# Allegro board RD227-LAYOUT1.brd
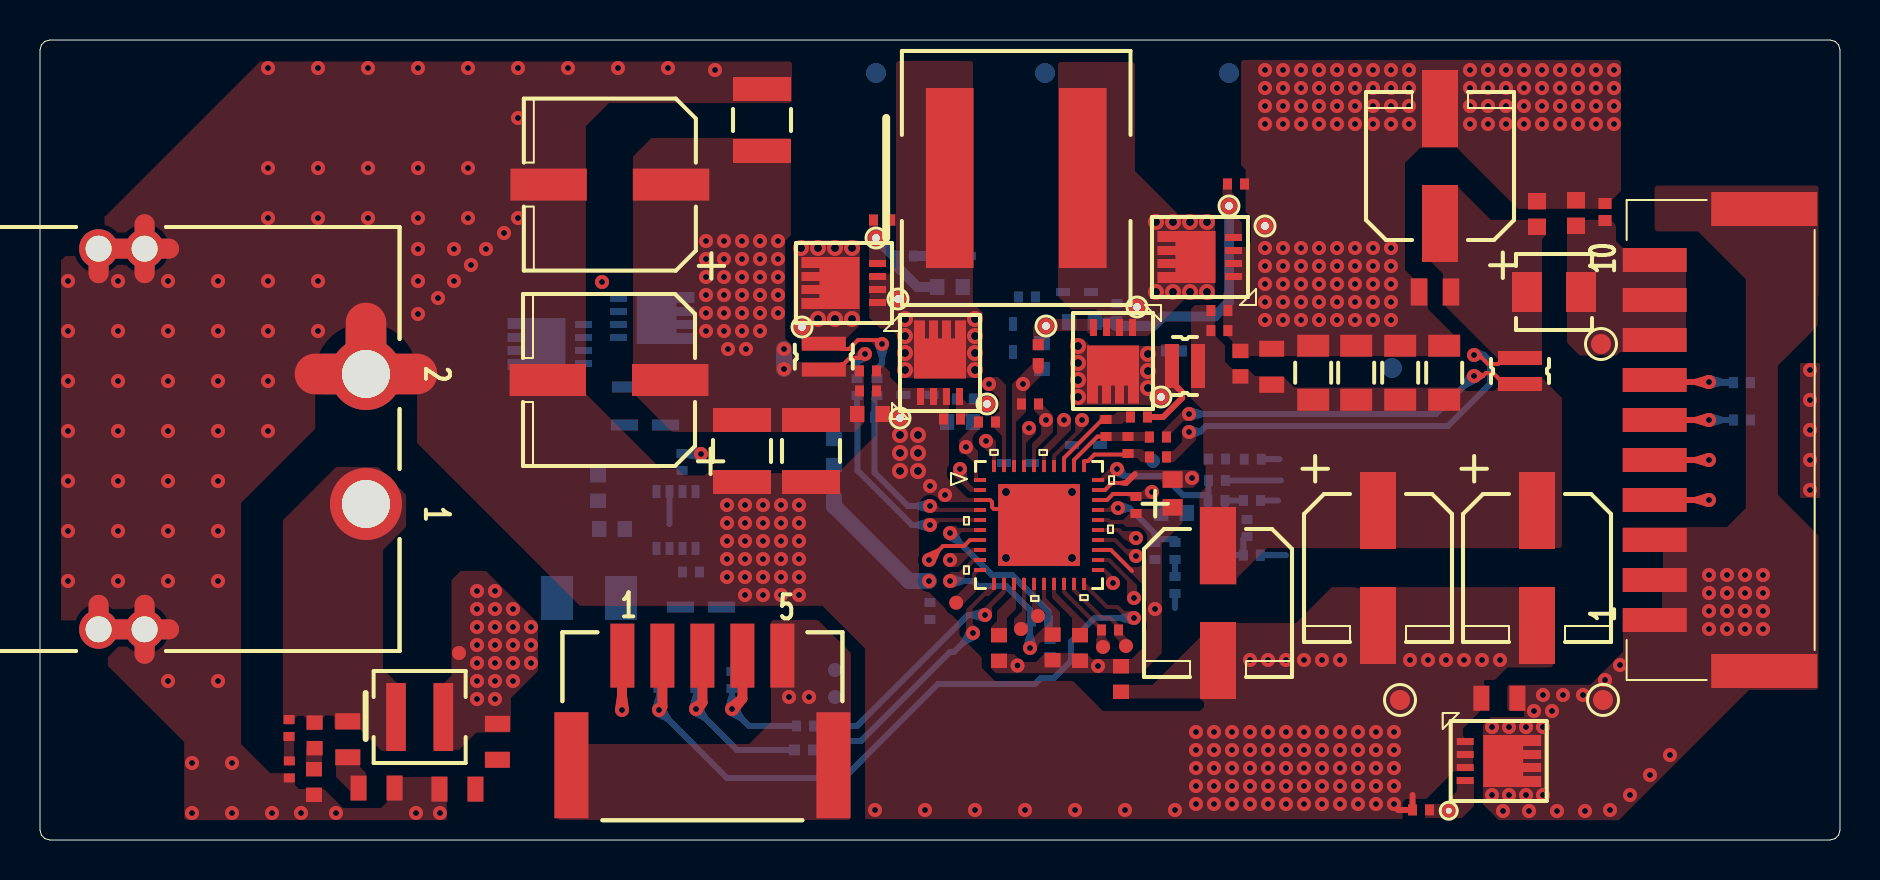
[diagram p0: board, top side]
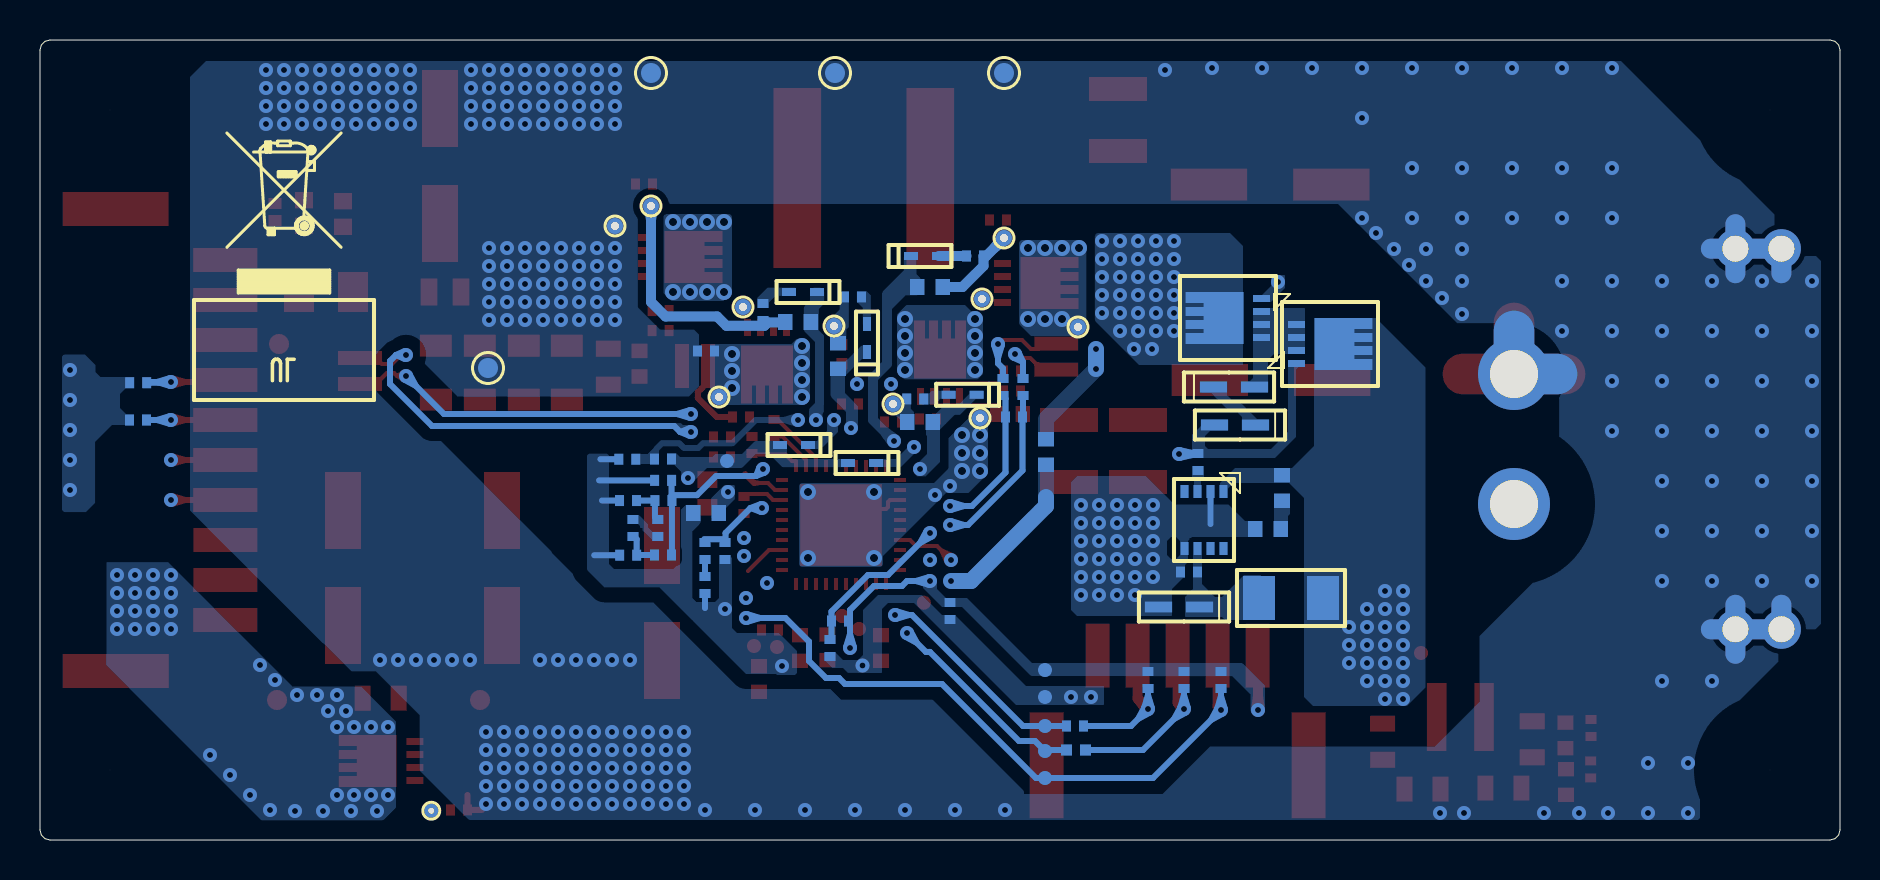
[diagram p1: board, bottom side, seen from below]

Outline 90 x 40 mm; copper layers: TOP, CONDUCTIVE2, CONDUCTIVE3, BOTTOM. Coordinates in mm from the lower left corner of the outline.
Outline path: 0,39.5 0.07,39.75 0.25,39.93 0.5,40 89.5,40 89.75,39.93 89.93,39.75 90,39.5 90,0.5 89.93,0.25 89.75,0.07 89.5,0 0.5,0 0.25,0.07 0.07,0.25 0,0.5 0,39.5

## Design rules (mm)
constraint set DEFAULT: 

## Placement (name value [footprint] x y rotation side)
C101  -  [KC00060AKP]  15.39 5.03 90 top
C102  -  [KC00060AKP]  16.83 2.6 180 top
C103  -  [KCK03340AKP]  36.1 36 270 top
C104  -  [KC00080AKP]  41.5 21.3 180 top
C105  -  [KC01340AKP]  13.73 5.23 90 top
C106  -  [KC01340AKP]  13.7 2.9 90 top
C107  -  [DC837K]  28.49 32.77 0 top
C108  -  [KCK03340AKP]  35.1 19.45 90 top
C109  -  [DC834K]  41.4 22.45 180 top
C110  -  [DC834K]  12.45 5.6 90 top
C111  -  [DC834K]  12.47 3.53 90 top
C112  -  [DC837K]  28.45 23 0 top
C113  -  [KCK03340AKP]  38.55 19.45 90 top
C114  -  [DC834K]  41.4 23.45 180 top
C115  -  [KC00060AKP]  22.87 4.91 90 top
C116  -  [KC00060AKP]  20.87 2.55 0 top
C117  -  [DC834K]  47.35 20.9 0 top
C118  -  [DC834K#2]  32.55 13.4 0 bottom
C119  -  [KC01540AKP01#2]  56.7 24.45 180 bottom
C120  -  [DC834K]  49.5 21.8 180 top
C121  -  [KC00080AKP#2]  27.9 17.6 270 bottom
C122  -  [KC00080AKP#2]  28.6 15.55 0 bottom
C123  -  [DC843R]  58.9 11.85 90 top
C124  -  [KC00140AKP]  70.21 23.36 270 top
C125  -  [KC00060AKP]  61.58 23.66 270 top
C126  -  [DC843R]  74.85 13.6 90 top
C127  -  [KC00140AKP]  68.01 23.36 270 top
C128  -  [KC00080AKP]  60.02 23.82 270 top
C129  -  [DC843R]  66.9 13.6 90 top
C130  -  [KC00140AKP]  65.81 23.36 270 top
C131  -  [DC834K]  58.97 25.47 180 top
C132  -  [KC00140AKP]  63.66 23.36 270 top
C133  -  [KC01540AKP01]  58.97 26.47 180 top
C134  -  [KCK02380AKP01]  74.85 31.3 270 top
C135  -  [DC843R]  70 33.7 270 top
C136  -  [KCK02380AKP01]  76.8 31.35 270 top
C137  -  [KC01540AKP01]  78.25 31.4 270 top
C138  -  [KC00060AKP]  72.97 7.09 0 top
C139  -  [KC00080AKP#2]  56.7 16.35 0 bottom
C140  -  [DC834K]  54.8 16.75 90 top
C141  -  [DC834K#2]  44.5 11.45 270 bottom
C142  -  [KC01670AKP]  50.63 9.63 270 top
C143  -  [KC01560AKP]  56.63 17.33 270 top
C144  -  [DC834K#2]  41.3 21.15 180 bottom
C145  -  [KC00080AKP]  47.95 9.6 270 top
C146  -  [KC00080AKP]  52 9.6 270 top
C147  -  [DC834K]  53.3 20.6 90 top
C148  -  [DC834K]  54.4 19.75 90 top
C149  -  [DC834K#2]  85.1 21 0 bottom
C150  -  [DC834K#2]  85.09 22.86 0 bottom
C151  -  [DC834K#2]  55.75 14.45 270 bottom
C152  -  [DC834K#2]  56.75 12.75 270 bottom
C153  -  [DC834K#2]  58.85 17.98 0 bottom
C154  -  [DC834K#2]  60.6 16.97 0 bottom
C155  -  [DC834K#2]  60.35 15.6 270 bottom
CN101  -  [LOCAL_HVH_280_2P_6_5_1]  16.3 16.8 270 top
CN102  -  [LOCAL_502352_0501]  33.12 5.69 0 top
CN103  -  [LOCAL_502352_1000]  84 20 90 top
D101  -  [D8K022]  33.05 11.65 180 bottom
D102  -  [D8101D1AKP]  48.9 18.85 180 bottom
D103  -  [D8101D1AKP]  45.75 29.2 0 bottom
D104  -  [D8101D1AKP]  43.87 22.26 180 bottom
D105  -  [D8101D1AKP]  48.65 25.1 270 bottom
D106  -  [D8101D1AKP]  51.85 27.4 180 bottom
D107  -  [D8101D1AKP]  52.3 19.75 180 bottom
D108  -  [D8K022]  30.25 20.75 180 bottom
D109  -  [D8K022]  30.3 22.65 0 bottom
FL101  -  [KC00080AKP#2]  39.7 19.4 90 bottom
IC101  -  [SN00281AKP]  31.8 16 0 bottom
IC102  -  [LOCAL_MAX25432BATLGV_1]  49.95 15.75 0 top
L101  -  [LOCAL_XEL_4030_471ME_1]  18.98 6.15 0 top
L102  -  [LOCAL_XAL1010_472MED]  48.81 33.1 0 top
L103  -  [LOCAL_IHLP1212BZEVR2_1]  75.7 27.4 0 top
NOREF  -  [unnamed]  86.5 36.5 0 top
NOREF#2  -  [unnamed]  3.5 3.5 0 top
NOREF#3  -  [unnamed]  3.5 36.5 0 top
NOREF#4  -  [unnamed]  86.5 3.5 0 top
NOREF#5  -  [#2]  77.8 31.35 180 bottom
NOREF#6  -  [#2]  73.3 22 180 bottom
Q101  -  [SN00612AKP]  25.5 24.8 270 bottom
Q102  -  [SN00612AKP]  30.6 26.1 90 bottom
Q103  -  [SN00612AKP]  40.2 27.85 90 top
Q104  -  [SN00612AKP]  45 23.85 0 top
Q105  -  [SN00612AKP]  53.65 23.95 180 top
Q106  -  [SN00612AKP]  58 29.15 90 top
Q107  -  [SN00612AKP]  72.94 3.95 270 top
R101  -  [KC00080AKP#2]  46 20.9 0 bottom
R102  -  [KC00080AKP#2]  45.5 27.65 180 bottom
R103  -  [DC934K#3]  43.25 29.2 180 bottom
R104  -  [LOCAL_KRL2012]  39.19 24.17 90 top
R105  -  [LOCAL_KRL2012]  57.25 23.7 0 top
R106  -  [LOCAL_KRL2012]  74 23.45 90 top
R107  -  [DC934K#3]  46.24 22.05 0 bottom
R108  -  [DC934K]  42.1 31 180 top
R109  -  [DC934K]  45.6 21.05 0 top
R110  -  [DR820RF]  27.45 12.1 0 bottom
R111  -  [DC934K#2]  49.91 24.29 90 top
R112  -  [DC934K]  59.8 32.8 180 top
R113  -  [DC934K#3]  49.35 27.15 0 bottom
R114  -  [DC934K#3]  53.85 26.4 270 bottom
R115  -  [KC00080AKP#2]  50.1 24.2 90 bottom
R116  -  [KC00080AKP#2]  52.1 25.9 0 bottom
R117  -  [DR824K#2]  32.1 18.9 270 bottom
R119  -  [DR810K]  69.75 27.4 0 top
R120  -  [DR824K]  69.05 1.5 0 top
R121  -  [DR824K#2]  34.6 8 90 bottom
R122  -  [DR824K#2]  32.8 8 90 bottom
R123  -  [DC934K#3]  41.85 22.65 270 bottom
R124  -  [DC934K#3]  40.85 22.65 270 bottom
R125  -  [DR824K#2]  30.95 8 90 bottom
R126  -  [DR824K]  53.5 10.5 180 top
R127  -  [DC934K#4]  38.2 4.5 0 bottom
R128  -  [DC934K#3]  38.25 5.7 0 bottom
R129  -  [KC00080AKP]  54.05 8.05 90 top
R130  -  [DC934K]  54.95 21.15 180 top
R131  -  [DC934K]  55.9 20.15 180 top
R132  -  [DC934K]  55.9 19.15 180 top
R133  -  [DR824K#2]  56.75 14.45 270 bottom
R134  -  [DC934K#3]  50 10.95 180 bottom
R135  -  [DR824K#2]  50.5 9.6 90 bottom
R136  -  [KC00050AKP]  58.83 16.97 0 bottom
R137  -  [DC934K#3]  60.64 19.04 180 bottom
R138  -  [DR824K#2]  59.11 15.6 270 bottom
R139  -  [DR824K#2]  58.85 19.05 180 bottom
R140  -  [DR824K#2]  58.85 14.25 0 bottom
R141  -  [DR824K#2]  60.59 14.24 0 bottom
TP101  -  [TL0_7_A_NOMM]  20.95 9.35 0 top
TP102  -  [TL0_7_A_NOMM]  39.7 17.15 180 bottom
TP103  -  [LOCAL_TL0_4_TH_A]  38.1 25.65 180 bottom
TP104  -  [LOCAL_TL0_4_TH_A]  41.8 30.1 180 bottom
TP105  -  [LOCAL_TL0_4_TH_A]  42.9 27.05 180 bottom
TP106  -  [LOCAL_TL0_4_TH_A]  47.35 21.8 0 top
TP107  -  [LOCAL_TL0_4_TH_A]  43 21.1 0 top
TP108  -  [LOCAL_TL0_4_TH_A]  56.05 22.15 0 top
TP109  -  [LOCAL_TL0_4_TH_A]  50.3 25.7 180 bottom
TP110  -  [LOCAL_TL0_4_TH_A]  54.85 26.65 180 bottom
TP111  -  [LOCAL_TL0_4_TH_A]  59.45 31.7 180 bottom
TP112  -  [LOCAL_TL0_4_TH_A]  61.25 30.7 180 bottom
TP113  -  [LOCAL_TP_100_A]  78.05 24.8 0 top
TP114  -  [LOCAL_TL0_4_TH_A]  70.44 1.46 0 top
TP115  -  [LOCAL_TP_100_A]  78.15 7 0 top
TP116  -  [LOCAL_TP_100_A]  68 7 0 top
TP117  -  [TL0_7_A_NOMM]  39.75 8.5 180 bottom
TP118  -  [TL0_7_A_NOMM]  39.75 7.15 180 bottom
TP119  -  [TL0_7_A_NOMM]  55.65 18.95 180 bottom
TP120  -  [TL0_7_A_NOMM]  54.3 9.7 0 top
TP121  -  [TL0_7_A_NOMM]  53.15 9.65 0 top
TP122  -  [TL0_7_A_NOMM]  39.75 3.1 180 bottom
TP123  -  [TL0_7_A_NOMM]  39.75 4.45 180 bottom
TP124  -  [TL0_7_A_NOMM]  39.75 5.7 180 bottom
TP125  -  [TL0_7_A_NOMM]  45.81 11.86 0 top
TP126  -  [TL0_7_A_NOMM]  49.05 10.55 0 top
TP127  -  [TL0_7_A_NOMM]  49.9 11.2 0 top
TP131  -  [LOCAL_TP_100_A]  67.6 23.6 180 bottom
TP132  -  [LOCAL_TP_100_A]  59.45 38.35 180 bottom
TP133  -  [LOCAL_TP_100_A]  50.25 38.35 180 bottom
TP134  -  [LOCAL_TP_100_A]  41.8 38.35 180 bottom

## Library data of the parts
C101 C102 C115 C116 = GDM03S00003P: alternate symbols: (T:KC00060AKP;B:KC00060BKP)
C103 C108 C113 = GAS030000261: alternate symbols: (T:KCK03340AKP;B:KCK03340BKP)
C104 C121 C122 C128 C139 C145 C146 = GDM03S000024: alternate symbols: (T:KC00080AKP;B:KC00080BKP)
C105 C106 = GAS030000041: alternate symbols: (T:KC01340AKP;B:KC01340BKP)
C107 C112 = GDM030001780: alternate symbols: (T:DC837K;B:DC937K)
C109 C114 C117 C118 C120 C131 C140 C141 C155 = G924015104Q0: alternate symbols: (T:DC834K;B:DC934K)
C110 C111 = G5103106P106: alternate symbols: (T:DC834K;B:DC934K)
C119 C133 C137 = GAS030000078: alternate symbols: (T:KC01540AKP01,DC834K,KC01540AKP;B:KC01540BKP01,DC834K,KC01540BKP)
C123 C126 C129 C135 = GDM030000304: alternate symbols: (T:DC843R;B:DC943R)
C124 C127 C130 C132 = GDM03S000017: alternate symbols: (T:KC00140AKP;B:KC00140BKP)
C125 C138 = GDM03S000036: alternate symbols: (T:KC00060AKP;B:KC00060BKP)
C134 C136 = GAS030000086: alternate symbols: (T:KCK02380AKP01;B:KCK02380BKP01)
C142 = GDM030002537: alternate symbols: (T:KC01670AKP;B:KC01670BKP)
C143 = GDM030002140: alternate symbols: (T:KC01560AKP;B:KC01560BKP)
C144 C147 C148 C151 = G5103105X103: alternate symbols: (T:DC834K;B:DC934K)
C149 C150 = G5103106G107: alternate symbols: (T:DC834K;B:DC934K)
C152 = G36030133517: alternate symbols: (T:DC834K;B:DC934K)
C153 = G510310FQ104: alternate symbols: (T:DC834K;B:DC934K)
C154 = G510310E1104: alternate symbols: (T:DC834K;B:DC934K)
CN101 = HVH-280-2P-6_5DS: alternate symbols: (T:Local_HVH_280_2P_6_5_1;B:Local_HVH_280_2P_6_5_1_B)
CN102 = 502352-0501: alternate symbols: (T:Local_502352_0501;B:Local_502352_0501_B)
CN103 = 502352-1000: alternate symbols: (T:Local_502352_1000;B:Local_502352_1000_B)
D101 D108 D109 = K4200015: alternate symbols: (T:D8K022;B:D9K022)
D102-D107 = GDM42S000008: alternate symbols: (T:D8101D1AKP;B:D8101D1BKP)
FL101 = GDM130000101: alternate symbols: (T:KC00080AKP;B:KC00080BKP)
IC101 = GDM410000462: alternate symbols: (T:SN00281AKP;B:SN00281BKP)
IC102 = MAX25432BATLGV+
L101 = XEL-4030-471MEC: alternate symbols: (T:Local_XEL_4030_471ME_1;B:Local_XEL_4030_471ME_1_B)
L102 = XAL1010-472MED: alternate symbols: (T:Local_XAL1010_472MED;B:Local_XAL1010_472MED_B)
L103 = IHLP1212BZEVR22M5A: alternate symbols: (T:Local_IHLP1212BZEVR2_1;B:Local_IHLP1212BZEVR2_1_B)
Q101-Q107 = K4100929: alternate symbols: (T:SN00612AKP;B:SN00612BKP)
R101 R102 R115 R116 R129 = G8800256207A: alternate symbols: (T:KC00080AKP;B:KC00080BKP)
R103 R107-R109 R111-R114 R123 R124 R127 R128 R130-R132 R134 R137 = GAS010000128: alternate symbols: (T:DC934K,DR824K,KC01310AKP,DR924K;B:DC934K,DR824K,KC01310BKP,DR924K)
R104 R105 = KRL2012E-M-R003-F
R106 = KRL2012E-M-R005-F: alternate symbols: (T:Local_KRL2012;B:Local_KRL2012_B)
R110 = G510110RM109: alternate symbols: (T:DR820RF;B:DR901RF)
R117 = G510110CB102: alternate symbols: (T:DR824K;B:DR924K)
R119 = G510110AC101: alternate symbols: (T:DR810K;B:DR910K)
R120 R125 = G510110EF108: alternate symbols: (T:DR824K;B:DR924K)
R121 R122 = G510110E7102: alternate symbols: (T:DR824K;B:DR924K)
R126 R133 R135 R138-R141 = G510110M9109: alternate symbols: (T:DR824K;B:DR924K)
R136 = GDM010002829: alternate symbols: (T:KC00050AKP;B:KC00050BKP)
TP101 TP102 TP117-TP127 = TL0.7_noMM: alternate symbols: (T:TL0_7_A_noMM;B:TL0_7_B_noMM)
TP103-TP112 TP114 = TL0.4_TH: alternate symbols: (T:Local_TL0_4_TH_A,Local_TL0_3_TH_A;B:Local_TL0_4_TH_B,Local_TL0_3_TH_B)
TP113 TP115 TP116 TP131-TP134 = TP-100: alternate symbols: (T:Local_TP_100_A;B:Local_TP_100_B)

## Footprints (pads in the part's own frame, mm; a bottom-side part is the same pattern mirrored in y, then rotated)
D8K022
  rect 1.36x0.55 smd: A(-1.025,0) C(1.025,0)
D8101D1AKP
  rect 0.7x0.4 smd: A(-0.7,0) C(0.7,0)
DC834K
  rect 0.45x0.55 smd: 1(-0.425,0) 2(0.425,0)
DC834K#2
  rect 0.45x0.55 smd: 1(0.425,0) 2(-0.425,0)
DC837K
  rect 3.82x1.6 smd: 1(-3.06,0) 2(3.06,0)
DC843R
  rect 3.85x1.8 smd: 1(-2.875,0) 2(2.875,0)
DC934K
  rect 0.45x0.55 smd: 1(-0.425,0) 2(0.425,0)
DC934K#2
  rect 0.55x0.55 smd: 1(-0.475,0) 2(0.475,0)
DC934K#3
  rect 0.45x0.55 smd: 1(0.425,0) 2(-0.425,0)
DC934K#4
  rect 0.55x0.55 smd: 1(0.475,0) 2(-0.475,0)
DR810K
  rect 0.83x1.35 smd: 1(-0.8,0) 2(0.8,0)
DR820RF
  rect 1.6x2.2 smd: 1(1.6,0) 2(-1.6,0)
DR824K
  rect 0.45x0.55 smd: 1(-0.425,0) 2(0.425,0)
DR824K#2
  rect 0.45x0.55 smd: 1(0.425,0) 2(-0.425,0)
KC00050AKP
  rect 0.45x0.55 smd: 1(0.425,0) 2(-0.425,0)
KC00060AKP
  rect 0.8x1.25 smd: 1(-0.9,0) 2(0.9,0)
KC00080AKP
  rect 0.72x0.8 smd: 1(-0.64,0) 2(0.64,0)
KC00080AKP#2
  rect 0.72x0.8 smd: 1(0.64,0) 2(-0.64,0)
KC00140AKP
  rect 1.1x1.6 smd: 1(-1.35,0) 2(1.35,0)
KC01340AKP
  rect 0.72x0.8 smd: 1(-0.64,0) 2(0.64,0)
KC01540AKP01
  rect 0.55x0.65 smd: 1(-0.425,0) 2(0.425,0)
KC01540AKP01#2
  rect 0.45x0.55 smd: 1(0.425,0) 2(-0.425,0)
KC01560AKP
  rect 0.83x1 smd: 1(-0.695,0) 2(0.695,0)
KC01670AKP
  rect 0.72x0.8 smd: 1(-0.64,0) 2(0.64,0)
KCK02380AKP01
  rect 0.82x0.9 smd: 1(-0.64,0) 2(0.64,0)
KCK03340AKP
  rect 1.2x2.9 smd: 1(-1.55,0) 2(1.55,0)
LOCAL_502352_0501
  rect 1.2x3.2 smd: 1(-4,3.53) 2(-2,3.53) 3(0,3.53) 4(2,3.53) 5(4,3.53)
  rect 1.7x5.3 smd: 1T(-6.55,-1.95) 2T(6.55,-1.95)
LOCAL_502352_1000
  rect 1.2x3.2 smd: 1(-9,3.265) 2(-7,3.265) 3(-5,3.265) 4(-3,3.265) 5(-1,3.265) 6(1,3.265) 7(3,3.265) 8(5,3.265) 9(7,3.265) 10(9,3.265)
  rect 1.7x5.3 smd: 1T(-11.55,-2.215) 2T(11.55,-2.215)
LOCAL_HVH_280_2P_6_5_1
  round 3.6 hole 2.4: 1(0,0) 2(-6.5,0)
  round 1.95 hole 1.3: 1T(6.265,-13.37) 2T(6.265,-11.07) 3T(-12.765,-11.07) 4T(-12.765,-13.37)
LOCAL_IHLP1212BZEVR2_1
  custom 0.375x0.375 smd: 1(-1.35,0) 2(1.35,0)
LOCAL_KRL2012
  custom 0.175x0.175 smd: 1(-0.65,0) 2(0.65,0)
LOCAL_MAX25432BATLGV_1
  custom 0.05x0.05 smd: 1(-2.948,2.25) 2(-2.948,1.75) 3(-2.948,1.25) 4(-2.948,0.75) 5(-2.948,0.25) 6(-2.948,-0.25) 7(-2.948,-0.75) 8(-2.948,-1.25) 9(-2.948,-1.75) 10(-2.948,-2.25) 11(-2.25,-2.948) 12(-1.75,-2.948) 13(-1.25,-2.948) 14(-0.75,-2.948) 15(-0.25,-2.948) 16(0.25,-2.948) 17(0.75,-2.948) 18(1.25,-2.948) 19(1.75,-2.948) 20(2.25,-2.948) 21(2.948,-2.25) 22(2.948,-1.75) 23(2.948,-1.25) 24(2.948,-0.75) 25(2.948,-0.25) 26(2.948,0.25) 27(2.948,0.75) 28(2.948,1.25) 29(2.948,1.75) 30(2.948,2.25) 31(2.25,2.948) 32(1.75,2.948) 33(1.25,2.948) 34(0.75,2.948) 35(0.25,2.948) 36(-0.25,2.948) 37(-0.75,2.948) 38(-1.25,2.948) 39(-1.75,2.948) 40(-2.25,2.948)
  custom 1.022x1.022 smd: 41(0,0)
LOCAL_TL0_4_TH_A
  round 0.7 hole 0.3: 1(0,0)
LOCAL_TP_100_A
  custom 0.25x0.25 smd: 1(0,0)
LOCAL_XAL1010_472MED
  custom 0.595x0.595 smd: 1(-3.325,0) 2(3.325,0)
LOCAL_XEL_4030_471ME_1
  custom 0.245x0.245 smd: 1(-1.185,0) 2(1.185,0)
SN00281AKP
  rect 0.4x0.65 smd: 1(-0.975,-1.425) 2(-0.325,-1.425) 3(0.325,-1.425) 4(0.975,-1.425) 5(0.975,1.425) 6(0.325,1.425) 7(-0.325,1.425) 8(-0.975,1.425)
SN00612AKP
  rect 0.35x0.85 smd: 1(-0.975,-1.675) 2(-0.325,-1.675) 3(0.325,-1.675) 4(0.975,-1.675)
  custom 0.65x0.65 smd: 5(0,0.675)
TL0_7_A_NOMM
  round 0.7 smd: 1(0,0)
unnamed
  round 0.01 hole 3 unplated: (0,0)

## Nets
GND_A: C139.1 C140.1 C141.1 C142.2 C143.2 C145.2 C146.2 C149.1 C150.1 C151.1 C152.1 C153.1 C154.1 CN102.1T CN102.2T CN102.5 IC102.23 IC102.26 R129.2 R135.2 R137.2 R141.1 TP118.1
GND_P: C102.1 C103.1 C104.1 C106.1 C107.1 C108.1 C109.1 C111.1 C112.1 C113.1 C114.1 C116.1 C118.1 C119.2 C122.1 C123.1 C124.1 C125.1 C126.1 C127.1 C128.1 C129.1 C130.1 C131.1 C132.1 C133.1 C134.1 C135.1 C136.1 C137.1 C138.1 CN101.1T CN101.2 CN101.2T CN101.3T CN101.4T D101.A IC101.2 IC101.5 IC102.3 IC102.41 Q104.1 Q104.2 Q104.3 Q106.1 Q106.2 Q106.3 Q107.1 Q107.2 Q107.3 R109.1 R112.1 R119.1 R120.1 R129.1 TP107.1 TP112.1 TP116.1 TP131.1 TP132.1 TP133.1 TP134.1
VBAT: C139.2 C140.2 FL101.2 IC102.28 TP102.1
VBUS: C136.2 C137.2 CN103.8 CN103.9 CN103.10 L103.2 TP113.1
VDD: C141.2 C142.1 CN102.1 IC102.9 IC102.16 R121.1 R122.1 R125.1 R134.1 TP117.1
VIN: C101.2 C105.2 C110.2 CN101.1 L101.1
VIN2: C115.2 C121.2 IC101.1 L101.2 Q101.5 R110.2 TP101.1
ADDR: IC102.34 R137.1 R139.2
ALERT: CN102.2 IC102.20 R125.2 TP122.1
BIAS: C143.1 D102.A D107.A IC102.29 R139.1 TP119.1
BST1: C117.1 D102.C IC102.1
BST2: C120.1 D107.C IC102.36
CSN1: Q103.5 R104.2 R123.2 TP103.1
CSN2: C134.2 C135.2 L103.1 R106.2 R119.2 R132.1
CSP1: C103.2 C104.2 C107.2 C108.2 C109.2 C112.2 C113.2 C114.2 FL101.1 Q102.5 R104.1 R124.2
CSP2: C119.1 Q105.5 R105.1 R130.1 TP108.1
DH1: D103.C IC102.40 R102.2
DH1_Q: Q103.4 R102.1 R103.1 R108.2 TP104.1
DH2: D105.C IC102.37 R115.2
DH2_Q: Q105.4 R111.2 R113.1 R115.1 TP109.1
DL1: D104.C IC102.2 R101.2
DL1_Q: Q104.4 R101.1 R107.1 R109.2 TP106.1
DL2: D106.C IC102.35 R116.2
DL2_Q: Q106.4 R112.2 R114.1 R116.1 TP111.1
GDRV: IC102.8 Q107.4 R120.2 TP114.1
HVCC1: C150.2 CN103.7 IC102.25
HVCC2: C149.2 CN103.6 IC102.24
HVDM: CN103.5 IC102.21
HVDP: CN103.4 IC102.22
HVEN: IC102.6 R134.2 R135.1
LX1: C117.2 IC102.39 L102.1 Q103.1 Q103.2 Q103.3 Q104.5 R108.1 TP105.1
LX2: C120.2 IC102.38 L102.2 Q105.1 Q105.2 Q105.3 Q106.5 R111.1 TP110.1
OUT: C123.2 C124.2 C125.2 C126.2 C127.2 C128.2 C129.2 C130.2 C131.2 C132.2 C133.2 R105.2 R106.1 R131.1
SCL: CN102.3 R122.2 R127.2
SDA: CN102.4 R121.2 R128.2
SHLD_SNS: C138.2 CN103.1 CN103.1T CN103.2 CN103.2T CN103.3 IC102.7 Q107.5 TP115.1
SIG310: C151.2 IC102.27 R133.2
SIG311: C152.2 R133.1
SIG313: C154.2 R136.1 R138.2
SIG316: C155.1 R140.1 R141.2
SIG317: C155.2 R138.1
SIG318: C153.2 IC102.30 R136.2 R140.2
SIG319: C147.1 C148.2 IC102.32 R131.2
SIG324: C148.1 IC102.31 R132.2
SIG328: C147.2 IC102.33 R130.2
SIG335: C144.1 IC102.5 R124.1
SIG337: C144.2 IC102.4 R123.1
SIG341: IC102.10 TP125.1
SIG344: IC102.19 R126.1 TP120.1
SIG345: IC102.18 R126.2 TP121.1
SIG346: C145.1 IC102.13
SIG347: C146.1 IC102.17
SIG349: IC102.14 TP126.1
SIG350: IC102.15 TP127.1
SIG369: IC102.11 R127.1 TP123.1
SIG370: IC102.12 R128.1 TP124.1
SIG422: C118.2 D101.C IC101.6 R110.1
SIG424: D103.A R103.2
SIG425: D104.A R107.2
SIG426: D109.A Q101.1 Q101.2 Q101.3 Q102.1 Q102.2 Q102.3
SIG427: C101.1 C102.2
SIG428: C105.1 C106.2
SIG429: C110.1 C111.2
SIG432: C121.1 C122.2
SIG434: D105.A R113.2
SIG435: D106.A R114.2
SIG439: C115.1 C116.2
SIG446: IC101.3 R117.1
SIG449: D108.C D109.C
SIG450: D108.A Q101.4 Q102.4 R117.2

Pads without a net: IC101 4 7 8

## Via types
v1: diameter 0.7, hole 0.3, TOP to BOTTOM, 446 vias
v2: diameter 0.8, hole 0.4, TOP to BOTTOM, 40 vias

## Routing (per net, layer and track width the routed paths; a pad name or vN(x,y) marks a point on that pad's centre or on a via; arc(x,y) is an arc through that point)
GND_A: length 8.7
  TOP w0.2: 54.6,13.45 53.55,14.5 IC102.23
  BOTTOM w0.3: C154.1 61.9,16.97 ; C153.1 62.05,17.98 ; 61.11,19.04 61.98,19.04 ; R141.1 62.29,14.24 ; C152.1 56.75,11.6
  vias: v1(37.45,7.15) v1(38.45,7.15) v1(48.88,8.72) v1(52.9,8.7) v1(55.75,11.55) v1(88.5,23.5) v1(88.5,22) v1(88.5,20.5) v1(88.5,19) v1(88.5,17.5)
GND_P: length 97.7
  TOP w0.2: IC102.3 47.5,17 47.6,16.9 47.6,16.65 47.7,16.55 49.15,16.55 IC102.41
  TOP w0.3: 67.9,1.5 R120.1 68.63,2.25
  TOP w1: CN101.3T 5.23,28.34 ; CN101.3T CN101.4T 2.93,28.34 ; CN101.3T 6.46,29.57 ; CN101.3T 5.23,30.79 ; 2.93,11.76 CN101.1T CN101.2T ; CN101.2T 6.46,10.54 ; CN101.2T 5.23,9.31 ; CN101.2T 5.23,11.76
  TOP w2.032: CN101.2 18.85,23.3 ; CN101.2 16.3,25.85 ; CN101.2 13.75,23.3
  CONDUCTIVE2 w1: CN101.3T 5.23,28.09 ; CN101.3T 6.71,29.57 ; CN101.3T 5.23,31.04 ; CN101.3T CN101.4T 2.93,28.06 ; CN101.2T 5.23,9.06 ; CN101.2T 5.23,12.01 ; CN101.2T CN101.1T 2.93,12.01 ; CN101.2T 6.71,10.54
  CONDUCTIVE2 w2.032: CN101.2 16.3,25.6 ; CN101.2 14,23.3 ; CN101.2 16.3,21.6 ; CN101.2 18.6,23.3
  CONDUCTIVE3 w1: CN101.2T 6.71,10.54 ; CN101.2T 5.23,12.01 ; CN101.2T CN101.1T 2.93,12.01 ; CN101.2T 5.23,9.06 ; CN101.3T 5.23,31.04 ; CN101.3T CN101.4T 2.93,27.97 ; CN101.3T 5.23,27.97 ; CN101.3T 6.71,29.57
  CONDUCTIVE3 w2.032: 16.3,25.6 CN101.2 ; CN101.2 14,23.3 ; CN101.2 18.6,23.3 ; CN101.2 16.3,21.65
  BOTTOM w0.3: IC101.2 31.48,15.8
  BOTTOM w1: 6.46,29.57 CN101.3T ; CN101.3T 5.23,28.34 ; CN101.3T CN101.4T 2.93,28.34 ; CN101.3T 5.23,30.79 ; CN101.2T CN101.1T 2.93,11.76 ; CN101.2T 6.46,10.54 ; CN101.2T 5.23,11.76 ; CN101.2T 5.23,9.31
  BOTTOM w2.032: 14.15,23.3 CN101.2 16.3,25.45
  vias: v1(1.4,27.95) v1(1.4,25.45) v1(1.4,22.95) v1(1.4,20.45) v1(1.4,17.95) v1(1.4,15.45) v1(1.4,12.95) v1(3.9,27.95) v1(3.9,25.45) v1(3.9,22.95) v1(3.9,20.45) v1(3.9,17.95) v1(3.9,15.45) v1(3.9,12.95) v1(6.4,27.95) v1(6.4,25.45) v1(6.4,22.95) v1(6.4,20.45) v1(6.4,17.95) v1(6.4,15.45) v1(6.4,12.95) v1(6.4,7.95) v1(7.6,3.85) v1(7.6,1.35) v1(8.9,27.95) v1(8.9,25.45) v1(8.9,22.95) v1(8.9,20.45) v1(8.9,17.95) v1(8.9,15.45) v1(8.9,12.95) v1(8.9,7.95) v1(9.6,3.85) v1(9.6,1.35) v1(11.4,38.6) v1(11.4,33.6) v1(11.4,31.1) v1(11.4,27.95) v1(11.4,25.45) v1(11.4,22.95) v1(11.4,20.45) v1(11.6,1.35) v1(13.05,1.35) v1(13.9,38.6) v1(13.9,33.6) v1(13.9,31.1) v1(13.9,27.95) v1(13.9,25.45) v1(14.8,1.35) v1(16.4,38.6) v1(16.4,33.6) v1(16.4,31.1) v1(18.8,1.35) v1(18.9,38.6) v1(18.9,33.6) v1(18.9,31.1) v1(18.9,29.55) v1(18.9,27.95) v1(18.9,26.3) v1(19.9,27.1) v1(20,1.35) v1(20.7,29.55) v1(20.7,27.95) v1(21.4,38.6) v1(21.4,33.6) v1(21.4,31.1) v1(21.55,28.75) v1(22.3,29.55) v1(23.2,30.35) v1(23.9,38.6) v1(23.9,36.1) v1(23.9,31.1) v1(26.4,38.6) v1(28.9,38.6) v1(31.4,38.6) v1(33.75,38.5) v1(34.35,16.75) v1(34.35,15.85) v1(34.35,14.95) v1(34.35,14.05) v1(34.35,13.15) v1(35.25,16.75) v1(35.25,15.85) v1(35.25,14.95) v1(35.25,14.05) v1(35.25,13.15) v1(35.25,12.25) v1(36.15,16.75) v1(36.15,15.85) v1(36.15,14.95) v1(36.15,14.05) v1(36.15,13.15) v1(36.15,12.25) v1(37.05,16.75) v1(37.05,15.85) v1(37.05,14.95) v1(37.05,14.05) v1(37.05,13.15) v1(37.05,12.25) v1(37.95,16.75) v1(37.95,15.85) v1(37.95,14.95) v1(37.95,14.05) v1(37.95,13.15) v1(37.95,12.25) v1(41.75,1.5) v1(44.25,1.5) v1(44.5,17.7) v1(45.25,17.25) v1(46.75,1.5) v1(49.25,1.5) v1(51.75,1.5) v1(54.25,1.5) v1(56.75,1.5) v1(57.8,5.4) v1(57.8,4.5) v1(57.8,3.6) v1(57.8,2.7) v1(57.8,1.8) v1(58.7,5.4) v1(58.7,4.5) v1(58.7,3.6) v1(58.7,2.7) v1(58.7,1.8) v1(59.6,5.4) v1(59.6,4.5) v1(59.6,3.6) v1(59.6,2.7) v1(59.6,1.8) v1(60.5,9) v1(60.5,5.4) v1(60.5,4.5) v1(60.5,3.6) v1(60.5,2.7) v1(60.5,1.8) v1(61.25,38.5) v1(61.25,37.6) v1(61.25,36.7) v1(61.25,35.8) v1(61.25,29.6) v1(61.25,28.7) v1(61.25,27.8) v1(61.25,26.9) v1(61.25,26) v1(61.4,9) v1(61.4,5.4) v1(61.4,4.5) v1(61.4,3.6) v1(61.4,2.7) v1(61.4,1.8) v1(62.15,38.5) v1(62.15,37.6) v1(62.15,36.7) v1(62.15,35.8) v1(62.15,29.6) v1(62.15,28.7) v1(62.15,27.8) v1(62.15,26.9) v1(62.15,26) v1(62.3,9) v1(62.3,5.4) v1(62.3,4.5) v1(62.3,3.6) v1(62.3,2.7) v1(62.3,1.8) v1(63.05,38.5) v1(63.05,37.6) v1(63.05,36.7) v1(63.05,35.8) v1(63.05,29.6) v1(63.05,28.7) v1(63.05,27.8) v1(63.05,26.9) v1(63.05,26) v1(63.2,9) v1(63.2,5.4) v1(63.2,4.5) v1(63.2,3.6) v1(63.2,2.7) v1(63.2,1.8) v1(63.95,38.5) v1(63.95,37.6) v1(63.95,36.7) v1(63.95,35.8) v1(63.95,29.6) v1(63.95,28.7) v1(63.95,27.8) v1(63.95,26.9) v1(63.95,26) v1(64.1,9) v1(64.1,5.4) v1(64.1,4.5) v1(64.1,3.6) v1(64.1,2.7) v1(64.1,1.8) v1(64.85,38.5) v1(64.85,37.6) v1(64.85,36.7) v1(64.85,35.8) v1(64.85,29.6) v1(64.85,28.7) v1(64.85,27.8) v1(64.85,26.9) v1(64.85,26) v1(65,9) v1(65,5.4) v1(65,4.5) v1(65,3.6) v1(65,2.7) v1(65,1.8) v1(65.75,38.5) v1(65.75,37.6) v1(65.75,36.7) v1(65.75,35.8) v1(65.75,29.6) v1(65.75,28.7) v1(65.75,27.8) v1(65.75,26.9) v1(65.75,26) v1(65.9,5.4) v1(65.9,4.5) v1(65.9,3.6) v1(65.9,2.7) v1(65.9,1.8) v1(66.65,38.5) v1(66.65,37.6) v1(66.65,36.7) v1(66.65,35.8) v1(66.65,29.6) v1(66.65,28.7) v1(66.65,27.8) v1(66.65,26.9) v1(66.65,26) v1(66.8,5.4) v1(66.8,4.5) v1(66.8,3.6) v1(66.8,2.7) v1(66.8,1.8) v1(67.55,38.5) v1(67.55,37.6) v1(67.55,36.7) v1(67.55,35.8) v1(67.55,29.6) v1(67.55,28.7) v1(67.55,27.8) v1(67.55,26.9) v1(67.55,26) v1(67.7,5.4) v1(67.7,4.5) v1(67.7,3.6) v1(67.7,2.7) v1(67.7,1.8) v1(68.45,38.5) v1(68.45,37.6) v1(68.45,36.7) v1(68.45,35.8) v1(68.5,9) v1(69.4,9) v1(70.3,9) v1(71.2,9) v1(71.5,38.5) v1(71.5,37.6) v1(71.5,36.7) v1(71.5,35.8) v1(72.1,9) v1(72.4,38.5) v1(72.4,37.6) v1(72.4,36.7) v1(72.4,35.8) v1(73,9) v1(73.3,38.5) v1(73.3,37.6) v1(73.3,36.7) v1(73.3,35.8) v1(74.2,38.5) v1(74.2,37.6) v1(74.2,36.7) v1(74.2,35.8) v1(75.1,38.5) v1(75.1,37.6) v1(75.1,36.7) v1(75.1,35.8) v1(76,38.5) v1(76,37.6) v1(76,36.7) v1(76,35.8) v1(76.9,38.5) v1(76.9,37.6) v1(76.9,36.7) v1(76.9,35.8) v1(77.8,38.5) v1(77.8,37.6) v1(77.8,36.7) v1(77.8,35.8) v1(78.7,38.5) v1(78.7,37.6) v1(78.7,36.7) v1(78.7,35.8) v2(43,20.25) v2(43,19.35) v2(43,18.45) v2(43.9,20.25) v2(43.9,19.35) v2(43.9,18.45) v2(48.3,17.4) v2(48.3,14.1) v2(51.6,17.4) v2(51.6,14.1)
VBAT: length 9
  TOP w0.2: IC102.28 53.35,17 53.65,17.3 54.92,17.3
  BOTTOM w0.3: 55.65,17.45 v1(55.6,17.4)
  BOTTOM w0.8: v1(44.45,12.95) 43.45,12.95 39.7,16.7 TP102.1
VDD: length 9.2
  TOP w0.5: v1(29.1,6.5) 29.1,9.2
  BOTTOM w0.3: v1(45.5,12.95) 46.65,12.95 46.9,12.7 48.3,12.7 49.5,11.5 v1(49.5,9.6)
VIN2:
  vias: v1(21.85,12.45) v1(21.85,11.55) v1(21.85,10.65) v1(21.85,9.75) v1(21.85,8.85) v1(21.85,7.95) v1(21.85,7.05) v1(22.75,12.45) v1(22.75,11.55) v1(22.75,10.65) v1(22.75,9.75) v1(22.75,8.85) v1(22.75,7.95) v1(22.75,7.05) v1(23.65,11.55) v1(23.65,10.65) v1(23.65,9.75) v1(23.65,8.85) v1(23.65,7.95) v1(24.55,10.65) v1(24.55,9.75) v1(24.55,8.85)
ADDR:
  vias: v1(52.1,21)
ALERT: length 32.9
  TOP w0.5: v1(30.95,6.5) 31.12,6.67 CN102.2
  BOTTOM w0.3: R125.2 v1(30.95,6.5) 34.35,3.1 TP122.1 40.2,3.1 44.9,7.8 49.75,7.8 50.05,8.1 50.7,8.1 51.55,8.95 51.55,9.92 52.73,11.1 v1(54.7,11.1)
BIAS: length 2.2
  TOP w0.2: IC102.29 53.25,17.5 53.6,17.85 54.3,17.85
  TOP w0.3: 54.3,17.85 54.74,18.29
  vias: v1(57.6,18.1)
BST1:
  vias: v1(46.3,19.65)
BST2:
  vias: v1(50.3,21)
CSN1: length 4.1
  TOP w0.2: 40.05,24.55 40.45,24.55 40.9,25 41.9,25 v1(42.1,24.8)
  BOTTOM w0.3: R123.2 41.85,23.58 42.1,23.83 v1(42.1,24.8)
  vias: v2(38.05,29.6) v2(38.9,29.6) v2(38.9,26.05) v2(39.75,29.6) v2(39.75,26.05) v2(40.6,29.6) v2(40.6,26.05)
CSN2: length 19.7
  TOP w0.2: 73,23.9 72.9,23.8 72.4,23.8 72,24.2 72,24.25 v1(71.7,24.25)
  BOTTOM w0.3: v1(57.45,20.4) 57.99,20.4 58.29,20.7 70.4,20.7 72.5,22.8 72.5,23.95 72.2,24.25 v1(71.7,24.25)
CSP1: length 3.7
  TOP w0.2: 40.1,23.8 40.19,23.8 40.49,24.1 41.05,24.1 v1(41.25,24.3)
  BOTTOM w0.3: R124.2 40.85,23.9 v1(41.25,24.3)
  BOTTOM w0.8: v1(37.2,24.55) v1(37.2,23.55)
  vias: v1(33.3,29.95) v1(33.3,29.05) v1(33.3,28.15) v1(33.3,27.25) v1(33.3,26.35) v1(33.3,25.45) v1(34.2,29.95) v1(34.2,29.05) v1(34.2,28.15) v1(34.2,27.25) v1(34.2,26.35) v1(34.2,25.45) v1(34.4,24.55) v1(35.1,29.95) v1(35.1,29.05) v1(35.1,28.15) v1(35.1,27.25) v1(35.1,26.35) v1(35.1,25.45) v1(35.3,24.55) v1(36,29.95) v1(36,29.05) v1(36,28.15) v1(36,27.25) v1(36,26.35) v1(36,25.45) v1(36.9,29.95) v1(36.9,29.05) v1(36.9,28.15) v1(36.9,27.25) v1(36.9,26.35)
CSP2: length 4.3
  TOP w0.2: 56.85,23.45 R105.1 56.6,22.88
  TOP w0.3: 56.6,22.88 56.61,22.89 56.91,22.59 57.11,22.39 57.11,22.1 56.16,21.15 R130.1
  vias: v2(51.9,24.7) v2(51.9,23.85) v2(51.9,23) v2(51.9,22.15) v2(55.4,24.3) v2(55.4,23.45) v2(55.4,22.6)
DH1:
  vias: v1(47.3,19.95)
DH1_Q: length 4.4
  BOTTOM w0.5: R102.1 43.88,27.65 42.83,28.7 R103.1 42.69,29.2 41.79,30.1
DH2:
  vias: v1(49.45,20.6)
DH2_Q: length 0.1
  TOP w0.2: 50.38,25.62 50.45,25.7
DL1:
  vias: v1(46,18.55)
DL2:
  vias: v1(51.2,21)
DL2_Q: length 12.1
  BOTTOM w0.5: 52.71,25.88 53.61,25.88 53.78,25.71 55.68,25.71 56.15,26.18 58.72,26.18 59.45,26.9 TP111.1
GDRV: length 36.8
  CONDUCTIVE3 w0.3: TP114.1 71.75,2.78 71.75,4.85 69.65,6.95 48.25,6.95 46,9.2 46,11.3 46.35,11.65 46.35,13.15 v1(45.5,14)
HVCC1: length 37.1
  TOP w0.3: v1(83.45,22.9) 80.83,22.9 CN103.7
  CONDUCTIVE3 w0.3: v1(83.45,22.9) 75.65,15.1 v1(54.8,15.1)
  BOTTOM w0.3: 83.45,22.86 C150.2 84.63,22.9 v1(83.45,22.9)
HVCC2: length 35.3
  TOP w0.3: v1(83.45,21) CN103.6
  CONDUCTIVE3 w0.3: v1(83.45,21) 82.31,21 75.86,14.55 56.29,14.55 55.94,14.2 v1(54.8,14.2)
  BOTTOM w0.3: 84.59,21.02 84.57,21 v1(83.45,21)
HVDM: length 35.1
  TOP w0.3: v1(83.45,19) CN103.5
  CONDUCTIVE3 w0.3: v1(83.45,19) 77.37,12.92 54.52,12.92 54.45,12.85 v1(53.65,12.85)
HVDP: length 33.5
  TOP w0.3: CN103.4 v1(83.45,17)
  CONDUCTIVE3 w0.3: v1(83.45,17) 82.16,17 77.48,12.32 54.92,12.32 v1(54.7,12.1)
HVEN: length 8
  BOTTOM w0.3: R135.1 50.42,10.1 R134.2 50.42,11.43 48.6,13.25 47.6,13.25 v1(45.5,15.35)
LX1: length 9
  CONDUCTIVE2 w0.5: TP105.1 47.3,27.05 47.8,26.55 47.8,23.15 v1(47.45,22.8)
  vias: v2(43.25,26.05) v2(43.25,25.2) v2(43.25,24.35) v2(43.25,23.5) v2(46.75,26.05) v2(46.75,25.2) v2(46.75,24.35) v2(46.75,23.5)
LX2: length 11.3
  TOP w0.5: 49.91,23.56 R111.1
  CONDUCTIVE2 w0.5: 49.97,26.64 49.15,25.82 v1(49.15,22.8) ; 49.97,26.64 54.85,26.64 ; 49.97,26.64 49.98,26.65 51.91,26.65
  vias: v2(55.8,30.9) v2(55.8,27.4) v2(56.65,30.9) v2(56.65,27.4) v2(57.5,30.9) v2(57.5,27.4) v2(58.35,30.9) v2(58.35,27.4)
OUT: length 17.6
  TOP w0.2: v1(71.7,23.2) 72.15,23.2 72.29,23.34 72.66,23.34 73.21,22.8 R106.1
  BOTTOM w0.3: v1(57.45,21.3) 69.8,21.3 v1(71.7,23.2)
SCL: length 9.6
  TOP w0.5: v1(32.8,6.55) 33.12,6.87 CN102.3
  BOTTOM w0.3: R122.2 v1(32.8,6.55) 34.85,4.5 R127.2
SDA: length 7.5
  TOP w0.5: CN102.4 35.12,7.07 v1(34.6,6.55)
  BOTTOM w0.3: R121.2 v1(34.6,6.55) 35.45,5.7 R128.2
SHLD_SNS: length 38.3
  TOP w0.2: IC102.7 46.5,15 46.2,14.7 45.15,14.7 v1(44.45,14)
  CONDUCTIVE3 w0.3: 72.55,4.9 69.85,7.6 48.7,7.6 47.8,8.5 47.8,13.05 46.15,14.7 44.7,14.7 44.45,14.45 v1(44.45,14)
  vias: v1(72.6,5.65) v1(72.6,2.25) v1(73.15,1.45) v1(73.45,5.65) v1(73.45,2.25) v1(74.3,5.65) v1(74.3,2.25) v1(74.45,1.45) v1(74.7,6.45) v1(75.15,7.25) v1(75.15,5.65) v1(75.15,2.25) v1(75.6,6.45) v1(75.85,1.45) v1(76.15,7.25) v1(77.15,7.25) v1(77.25,1.45) v1(78.25,8) v1(78.5,1.5) v1(79,8.75) v1(79.5,2.25) v1(80.5,3.25) v1(81.5,4.25) v1(83.45,13.25) v1(83.45,12.35) v1(83.45,11.45) v1(83.45,10.55) v1(84.35,13.25) v1(84.35,12.35) v1(84.35,11.45) v1(84.35,10.55) v1(85.25,13.25) v1(85.25,12.35) v1(85.25,11.45) v1(85.25,10.55) v1(86.15,13.25) v1(86.15,12.35) v1(86.15,11.45) v1(86.15,10.55)
SIG310: length 3.7
  BOTTOM w0.3: v1(53.9,16.6) 54.47,16.6 55.72,15.35 55.72,15.03 55.73,15.04 56.78,15.04
SIG311: length 0.8
  BOTTOM w0.3: R133.1 C152.2
SIG313: length 1.9
  BOTTOM w0.3: C154.2 60.17,16.97 R136.1 59.25,16.17 R138.2
SIG316: length 1.9
  BOTTOM w0.3: 60.31,15.18 60.17,15.04 R141.2 60.16,14.25 R140.1
SIG318: length 9
  BOTTOM w0.3: v1(53.85,18.55) 54.2,18.2 56.19,18.2 57.15,17.24 58.42,17.24 ; 58.42,17.24 58.42,16.85 ; 58.42,17.24 C153.2 ; R136.2 58.4,14.27 R140.2
SIG319: length 1.9
  TOP w0.2: 51.7,18.95 51.7,19 52.88,20.18 53.1,20.18
SIG324: length 2.5
  TOP w0.2: 54.58,19.27 52.73,19.27 52.4,18.95 52.2,18.95
SIG328: length 3.1
  TOP w0.2: 53.17,20.95 53.11,21.01 51.2,19.1 51.2,18.8
SIG335: length 8.5
  BOTTOM w0.3: v1(44.5,15.75) 43.6,15.75 40.88,18.48 C144.1 40.85,21.18 R124.1
SIG337: length 7.4
  BOTTOM w0.3: v1(44.5,16.7) 43.4,16.7 41.73,18.38 C144.2 41.73,22.07 41.84,22.18 41.84,22.23 R123.1
SIG369: length 10.4
  BOTTOM w0.3: R127.1 39.7,4.5 TP123.1 40.25,4.95 41.05,4.95 45.5,9.4 45.7,9.4 v1(46.65,10.35)
SIG370: length 10.9
  BOTTOM w0.3: v1(47.25,11.25) 46.4,11.25 40.85,5.7 TP124.1 R128.1
SIG424: length 1.4
  BOTTOM w0.5: R103.2 D103.A
SIG450: length 11.6
  CONDUCTIVE3 w0.4: v1(33.05,19.3) 28.1,24.25 v1(28.1,27.9)
  BOTTOM w0.4: R117.2 32.12,19.3 v1(33.05,19.3) 33.08,19.3

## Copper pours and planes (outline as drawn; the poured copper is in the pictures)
GND_A on TOP: outline of 89 points within 47.55,8.34 57.13,17
GND_A on TOP: 88.05,17.1 88.01,17.11 88,17.15 88,23.8 88.01,23.84 88.05,23.85 88.95,23.85 88.99,23.84 89,23.8 89,17.15 88.99,17.11 88.95,17.1
GND_A on TOP: 26,1 25.89,1.04 25.85,1.15 25.85,4.65 25.89,4.76 26,4.8 35.45,4.8 36.55,5.9 36.55,10.85 36.59,10.96 36.7,11 38.84,11 38.94,10.96 40.51,9.39 40.55,9.29 40.55,1.15 40.51,1.04 40.4,1
GND_A on BOTTOM: 36.85,6.75 36.81,6.76 36.8,6.8 36.8,7.65 36.81,7.69 36.85,7.7 40.7,7.7 44.24,11.24 44.25,11.25 44.27,11.25 44.9,11.25 45.89,12.24 45.9,12.25 45.92,12.25 48.08,12.25 48.1,12.25 48.11,12.24 48.85,11.5 48.85,11.48 48.85,9.25 49.1,9 49.85,9 50.2,9.35 50.21,9.39 50.25,9.4 50.74,9.4 50.78,9.39 50.79,9.35 50.79,9.01 50.79,8.99 50.78,8.98 50.41,8.61 50.4,8.6 50.38,8.6 49.85,8.6 49.62,8.37 49.61,8.36 49.59,8.36 49.11,8.36 49.08,8.35 47.95,8.35 47.91,8.36 47.9,8.4 47.9,11.55 47.6,11.85 46.3,11.85 41.21,6.76 41.2,6.75 41.18,6.75
GND_A on BOTTOM: 52.3,8.25 52.19,8.29 52.15,8.4 52.15,9.43 52.15,9.45 52.16,9.46 53.04,10.34 53.05,10.35 53.07,10.35 55.15,10.35 55.4,10.6 55.4,14.05 55.44,14.16 55.55,14.2 55.9,14.2 56.01,14.16 56.05,14.05 56.05,12.1 56.25,11.9 57.19,11.9 57.39,12.1 57.39,15.43 57.07,15.74 57.05,15.77 57.03,15.81 56.98,15.86 56.97,15.87 56.96,15.89 56.96,16.7 56.98,16.74 57.01,16.75 57.69,16.75 57.71,16.75 57.73,16.74 57.94,16.53 57.95,16.51 57.95,16.49 57.95,14.66 57.91,14.54 57.9,14.45 57.9,14.05 57.98,13.82 58.18,13.69 58.2,13.68 58.33,13.55 61.3,13.55 61.55,13.8 61.55,19.17 61.59,19.27 61.7,19.32 62.5,19.32 62.61,19.27 62.65,19.17 62.65,13.56 62.64,13.5 62.61,13.46 61.8,12.65 61.78,12.63 61.76,12.63 59.03,12.63 57.41,11.01 57.39,11 57.37,10.99 57.37,10.98 57.36,10.96 54.71,8.31 54.7,8.3 54.68,8.3 53.2,8.3 53.16,8.26 53.15,8.25 53.13,8.25
GND_A on BOTTOM: 87.72,16.4 87.7,16.4 87.69,16.41 87.26,16.84 87.25,16.85 87.25,16.87 87.25,19.9 86.4,20.75 85.58,20.75 85.54,20.76 85.53,20.8 85.53,21.25 85.54,21.29 85.58,21.3 85.7,21.3 86,21.6 86,22.3 85.7,22.6 85.58,22.6 85.54,22.61 85.53,22.65 85.53,23.1 85.54,23.14 85.58,23.15 86.98,23.15 87.23,23.4 87.23,23.73 87.23,23.75 87.24,23.76 87.74,24.26 87.75,24.27 87.77,24.27 88.75,24.27 88.86,24.23 88.9,24.12 88.9,16.55 88.86,16.44 88.75,16.4
GND_A on CONDUCTIVE2: 48.35,10.38 48.35,10.4 48.36,10.41 48.84,10.89 48.85,10.9 48.87,10.9 52.55,10.9 59.24,17.59 59.25,17.6 59.27,17.6 75.23,17.6 82.46,24.83 82.5,24.85 82.53,24.86 87.9,24.86 87.93,24.85 87.97,24.83 88.92,23.88 88.94,23.85 88.95,23.81 88.95,17.29 88.94,17.25 88.92,17.22 86.53,14.83 86.51,14.82 86.49,14.81 82.78,14.81 78.31,10.34 78.3,10.33 78.28,10.33 56.88,10.33 54.91,8.36 54.9,8.35 54.88,8.35 48.69,8.35 48.68,8.35 48.66,8.36 48.36,8.66 48.35,8.68 48.35,8.69 ; 7 cut-outs
GND_A on CONDUCTIVE3: 48.35,12.43 48.35,12.45 48.36,12.46 48.72,12.82 48.74,12.83 48.76,12.84 52.03,12.84 52.93,13.73 52.93,15.23 52.94,15.25 52.95,15.26 53.81,16.13 53.83,16.14 53.85,16.14 54.11,16.21 54.31,16.39 54.32,16.39 54.44,16.51 54.45,16.52 54.47,16.52 56.12,16.52 57.23,17.64 57.25,17.65 57.27,17.65 75.28,17.65 82.46,24.83 82.5,24.85 82.53,24.86 87.75,24.86 87.78,24.85 87.82,24.83 88.87,23.78 88.89,23.75 88.9,23.71 88.9,17.29 88.89,17.25 88.87,17.22 86.48,14.83 86.46,14.82 86.44,14.81 82.78,14.81 78.31,10.34 78.3,10.33 78.28,10.33 57.13,10.33 55.03,8.23 55,8.21 54.96,8.2 48.72,8.2 48.7,8.2 48.69,8.21 48.36,8.54 48.35,8.55 48.35,8.57 ; 4 cut-outs
GND_P on TOP: 59.67,24.12 59.63,24.13 59.62,24.17 59.62,24.93 59.29,25.25 59.21,25.25 59.18,25.26 59.16,25.3 59.16,27.34 59.17,27.36 59.18,27.38 59.25,27.45 59.25,29.6 59.26,29.64 59.3,29.65 60.3,29.65 60.55,29.9 60.55,31.13 60.3,31.38 60.29,31.4 60.28,31.42 60.28,33.51 60.06,33.73 60.05,33.75 60.05,33.77 60.05,38.85 60.09,38.96 60.2,39 78.9,39 79.01,38.96 79.05,38.85 79.05,32.47 79.05,32.45 79.04,32.44 78.55,31.95 78.55,31.61 78.54,31.58 78.5,31.56 73.92,31.56 73.86,31.59 70.85,34.6 69,34.6 68.25,33.85 68.25,28.5 68.65,28.1 69.24,28.1 69.35,28.06 69.39,27.95 69.39,26.56 70.66,25.29 70.69,25.25 70.7,25.19 70.7,24.35 70.66,24.24 70.55,24.2 60.53,24.2 60.46,24.13 60.44,24.12 60.42,24.12
GND_P on TOP: outline of 267 points within 1.05,1 75.65,38.93
GND_P on BOTTOM: outline of 100 points within 0.95,1 82.5,38.95 ; 1 cut-out
GND_P on BOTTOM: 48,13.65 47.89,13.69 47.85,13.8 47.85,14.2 44.7,17.35 43.59,17.35 43.57,17.35 43.56,17.36 42.61,18.31 42.6,18.32 42.6,18.34 42.6,21.45 42.61,21.49 42.65,21.5 43.14,21.5 43.16,21.5 43.17,21.49 44.57,20.09 44.58,20.08 44.58,20.06 44.58,18.57 45.3,17.85 51.9,17.85 52.01,17.81 52.05,17.7 52.05,13.8 52.01,13.69 51.9,13.65
GND_P on BOTTOM: 32.61,13.89 32.6,13.9 32.6,13.92 32.6,14.95 32.4,15.15 29.05,15.15 29.01,15.16 29,15.2 29,15.9 29.01,15.94 29.05,15.95 29.75,15.95 30.56,16.76 30.58,16.77 30.6,16.77 33.27,16.77 34.69,18.19 34.7,18.2 34.72,18.2 38.13,18.2 38.15,18.2 38.16,18.19 38.44,17.91 38.45,17.9 38.45,17.88 38.45,11.52 38.45,11.5 38.44,11.49 38.16,11.21 38.15,11.2 38.13,11.2 33.45,11.2 33.41,11.21 33.4,11.25 33.4,12.55 32.76,13.19 32.75,13.2 32.75,13.22 32.75,13.75 ; 1 cut-out
GND_P on CONDUCTIVE2: outline of 208 points within 0.99,1 81.75,39 ; 12 cut-outs
GND_P on CONDUCTIVE3: outline of 121 points within 0.95,1.05 81.9,38.86 ; 14 cut-outs
GND_P on CONDUCTIVE3: 60.17,8.2 60.15,8.2 60.14,8.21 59.91,8.44 59.9,8.45 59.9,8.47 59.9,9.13 59.9,9.15 59.91,9.16 60.19,9.44 60.2,9.45 60.22,9.45 73.38,9.45 73.4,9.45 73.41,9.44 73.69,9.16 73.7,9.15 73.7,9.13 73.7,8.82 73.7,8.8 73.69,8.79 73.11,8.21 73.1,8.2 73.08,8.2
VBAT on BOTTOM: 55.79,16.08 55.75,16.09 55.74,16.13 55.74,16.58 55.72,16.58 55.7,16.59 55.28,17.01 55.27,17.03 55.26,17.05 55.26,17.7 55.28,17.74 55.31,17.75 55.76,17.75 55.78,17.75 55.8,17.74 56.42,17.11 56.43,17.09 56.44,17.07 56.44,16.13 56.42,16.09 56.39,16.08
VBAT on BOTTOM: 39.3,18.62 39.42,18.9 39.7,19.02 39.98,18.9 40.1,18.62 40.1,17.15 39.7,16.75 39.3,17.15
VBAT on CONDUCTIVE2: 44.86,11.86 44.71,11.89 44.58,11.97 44.17,12.38 44.08,12.51 44.05,12.66 44.05,12.95 44.45,13.35 44.85,12.95 44.85,12.83 45.02,12.66 51.71,12.66 53,13.95 53,14.8 53.02,14.91 53.09,15.01 55.25,17.17 55.25,17.22 55.34,17.43 55.55,17.52 55.58,17.52 55.79,17.43 55.88,17.22 55.88,17.08 55.86,16.96 55.79,16.87 53.95,15.03 53.95,15 53.95,14.07 53.92,13.91 53.83,13.78 52.02,11.97 51.89,11.89 51.74,11.86
VBUS on TOP: 77.05,24.22 76.99,24.23 76.95,24.26 76.39,24.82 76.36,24.87 76.35,24.92 76.35,30.85 76.39,30.96 76.5,31 78.49,31 78.59,30.96 78.76,30.79 78.8,30.69 78.8,29.95 79.15,29.6 82.15,29.6 82.26,29.56 82.3,29.45 82.3,24.55 82.26,24.44 82.15,24.4 79.01,24.4 78.87,24.26 78.82,24.23 78.77,24.22
VDD on TOP: 49.79,9.43 49.67,9.38 49.61,9.5 49.7,9.7 49.6,9.8 49.4,9.71 49.28,9.77 49.33,9.89 49.55,9.99 50.53,10.97 50.53,11.42 50.13,11.82 50.1,11.89 50.1,13.05 50.2,13.15 50.3,13.05 50.3,12.1 50.97,11.43 50.99,11.4 51,11.36 51,10 50.97,9.93 50.9,9.9 50.05,9.9 49.97,9.82
VDD on BOTTOM: 29.2,6.28 29.14,6.34 29.14,6.35 28.9,6.35 28.79,6.39 28.75,6.5 28.75,7.65 28.76,7.71 28.79,7.76 29.84,8.81 29.89,8.84 29.95,8.85 40.4,8.85 43.64,12.09 43.65,12.1 43.67,12.1 44.7,12.1 45.15,12.55 45.15,12.9 45.16,12.94 45.2,12.95 45.8,12.95 45.84,12.94 45.85,12.9 45.85,12.62 45.85,12.6 45.84,12.59 44.91,11.66 44.9,11.65 44.88,11.65 43.9,11.65 40.49,8.24 40.45,8.21 40.39,8.2 35.8,8.2 35.76,8.19 30.39,8.19 29.48,7.28 29.47,6.46 29.46,6.43 29.41,6.33 29.35,6.28 29.28,6.25
VIN on TOP: 17.14,4.46 17.08,4.47 17.03,4.51 16.03,5.51 14.86,5.51 14.76,5.55 14.71,5.66 14.71,6.14 14.63,6.22 14.27,6.22 14.15,6.1 14.15,5.66 14.11,5.55 14,5.51 13.46,5.51 13.35,5.55 13.31,5.66 13.31,6.08 13.18,6.21 12.88,6.21 12.75,6.08 12.75,5.91 12.71,5.81 12.6,5.76 12.31,5.76 12.2,5.81 12.16,5.91 12.16,6.2 12.15,6.23 12.14,6.26 12.14,15.93 12.16,15.98 12.19,16.03 14.76,18.61 14.87,18.65 16.85,18.65 16.96,18.61 18.26,17.3 18.3,17.2 18.3,15.71 18.29,15.65 18.26,15.61 17.15,14.5 17.15,8.55 17.85,7.85 18.15,7.85 18.26,7.81 18.3,7.7 18.3,4.61 18.26,4.51 18.15,4.46
VIN2 on TOP: 20.4,4.51 20.37,4.51 20.33,4.53 19.82,4.53 19.71,4.57 19.67,4.68 19.67,7.7 19.71,7.81 19.82,7.85 20.2,7.85 20.57,8.22 20.57,12.98 20.58,13 20.59,13.01 21.01,13.44 21.03,13.45 21.05,13.45 22.27,13.45 22.29,13.45 22.31,13.44 24.86,10.89 24.9,10.79 24.9,8.51 24.89,8.45 24.86,8.41 23.55,7.1 23.55,5.52 23.5,5.41 23.4,5.37 21.81,5.37 21,4.55 20.95,4.52 20.89,4.51
VIN2 on BOTTOM: 21.67,6.7 21.65,6.7 21.64,6.71 20.74,7.61 20.73,7.63 20.73,7.64 20.73,23.61 20.73,23.62 20.74,23.64 23.19,26.09 23.2,26.1 23.22,26.1 26.25,26.1 26.29,26.09 26.3,26.05 26.3,19.7 27.4,18.6 30.23,18.6 30.25,18.6 30.26,18.59 30.99,17.86 31,17.85 31,17.83 31,17.15 30.99,17.11 30.95,17.1 30.72,17.1 30.7,17.1 30.69,17.11 30.64,17.16 30.63,17.18 30.62,17.2 30.62,17.55 30.32,17.85 27.55,17.85 26.8,17.1 26.8,7.17 26.8,7.15 26.79,7.14 26.36,6.71 26.35,6.7 26.33,6.7
VIN2 on CONDUCTIVE2, CONDUCTIVE3: 21.5,6.65 21.46,6.66 21.45,6.7 21.45,12.85 21.46,12.89 21.5,12.9 23.13,12.9 23.15,12.9 23.16,12.89 24.94,11.11 24.95,11.1 24.95,11.08 24.95,8.32 24.95,8.3 24.94,8.29 23.31,6.66 23.3,6.65 23.28,6.65
ADDR on TOP: 50.6,19.2 50.61,19.24 50.63,19.27 51.75,20.4 51.75,20.91 51.78,20.98 51.85,21.01 52.33,21.01 52.4,20.98 52.43,20.91 52.43,20.87 52.42,20.83 52.4,20.8 52.2,20.6 52.19,20.56 52.17,20.53 50.8,19.16 50.8,18.95 50.7,18.85 50.6,18.95
ADDR on BOTTOM: 59.2,18.8 59.09,18.84 59.05,18.95 59.05,19.47 58.83,19.69 58.1,19.69 57.91,19.49 57.86,19.46 57.8,19.45 57.09,19.45 57.03,19.46 56.98,19.49 56.79,19.69 55.37,19.69 55.32,19.7 55.27,19.73 54.15,20.85 52.82,20.85 52.2,20.66 52.16,20.66 52.02,20.74 52.03,20.89 52.06,20.92 52.08,20.94 52.11,20.95 52.27,21 52.11,21.05 52.08,21.06 52.06,21.08 52.03,21.11 52.02,21.26 52.16,21.34 52.2,21.34 52.82,21.15 54.21,21.15 54.27,21.14 54.32,21.11 55.43,19.99 56.85,19.99 56.91,19.98 56.96,19.94 57.15,19.75 57.74,19.75 57.93,19.94 57.98,19.98 58.04,19.99 58.9,19.99 58.95,19.98 59.31,19.63 59.32,19.59 59.62,19.3 60.3,19.3 60.41,19.26 60.45,19.15 60.45,18.95 60.41,18.84 60.3,18.8
ALERT on TOP: 54.43,11 54.39,11.01 54.35,11.03 53.83,11.55 53.35,11.55 53.31,11.56 53.28,11.58 52.35,12.5 52.2,12.5 52.13,12.53 52.1,12.6 52.1,12.74 52.13,12.81 52.2,12.84 52.26,12.84 52.3,12.83 52.33,12.81 53.39,11.75 53.88,11.75 53.91,11.74 53.95,11.72 54.21,11.46 54.7,11.46 54.77,11.43 54.8,11.36 54.8,11.1 54.77,11.03 54.7,11
BIAS on BOTTOM: 57.34,17.95 57.3,17.96 57.27,17.98 56.65,18.6 55,18.6 54.9,18.62 54.82,18.67 54.2,19.3 53.54,19.3 52.92,18.67 52.88,18.65 52.85,18.64 49.52,18.64 49.45,18.67 49.42,18.74 49.42,18.95 49.45,19.02 49.52,19.05 52.45,19.05 52.65,19.25 52.65,19.7 52.72,19.88 52.9,19.95 54.15,19.95 54.25,19.93 54.33,19.88 54.9,19.3 56.21,19.3 56.25,19.29 56.28,19.27 56.4,19.15 58,19.15 58.17,19.32 58.2,19.34 58.24,19.35 58.5,19.35 58.57,19.32 58.6,19.25 58.6,18.86 58.57,18.79 58.5,18.76 58.29,18.76 57.94,18.41 57.94,18.05 57.91,17.98 57.84,17.95
BST1 on TOP: 46.77,17.9 46.75,17.9 46.73,17.92 46.72,17.93 46.7,17.95 46.7,17.97 46.7,18.85 46.25,19.3 46.07,19.3 46.05,19.3 46.04,19.31 45.96,19.39 45.95,19.4 45.95,19.42 45.95,19.98 45.95,20 45.96,20.01 46.79,20.84 46.8,20.85 46.82,20.85 47.1,20.85 47.14,20.84 47.15,20.8 47.15,20.64 47.14,20.61 47.11,20.59 47.01,20.56 46.92,20.5 46.75,20.33 46.68,20.23 46.62,20.07 46.62,19.77 46.79,19.55 46.88,19.45 46.9,19.44 46.9,19.41 46.9,18.1 47.15,18.1 47.19,18.09 47.2,18.05 47.2,17.95 47.19,17.91 47.15,17.9
CSN1 on TOP: 41.82,24.65 41.8,24.65 41.79,24.66 41.51,24.94 41.5,24.95 41.5,24.97 41.5,25.05 41.51,25.09 41.55,25.1 42.15,25.1 42.19,25.09 42.2,25.05 42.2,24.7 42.19,24.66 42.15,24.65
CSN1 on TOP: 38.2,24.6 38.09,24.64 38.05,24.75 38.05,25.15 37.66,25.53 37.65,25.55 37.65,25.57 37.65,29.53 37.65,29.55 37.66,29.56 38.09,29.99 38.1,30 38.12,30 40.85,30 40.96,29.96 41,29.85 41,25.81 40.96,25.7 40.3,25.05 40.3,24.75 40.26,24.64 40.15,24.6
CSN2 on TOP: 72.95,23.8 72.91,23.81 72.9,23.85 72.9,24.05 70.19,26.76 70.16,26.8 70.15,26.86 70.15,28.3 69.14,29.31 69.11,29.35 69.1,29.41 69.1,32.55 69.14,32.66 69.25,32.7 70.79,32.7 70.85,32.69 70.89,32.66 72.55,31 75.25,31 75.29,30.99 75.3,30.95 75.3,30.27 75.3,30.25 75.29,30.24 75.1,30.05 75.1,23.85 75.09,23.81 75.05,23.8
CSP1 on TOP: 40.7,24 40.66,24.01 40.65,24.05 40.65,24.18 40.65,24.2 40.66,24.21 41.09,24.64 41.1,24.65 41.12,24.65 41.25,24.65 41.29,24.64 41.3,24.6 41.3,24.05 41.29,24.01 41.25,24
CSP1 on TOP: 29.69,22.31 29.66,22.36 29.65,22.41 29.65,34.16 29.65,34.18 29.66,34.19 30.56,35.09 30.57,35.1 30.59,35.1 37.49,35.1 37.53,35.09 37.54,35.05 37.54,30.26 37.54,30.24 37.53,30.23 37.26,29.96 37.26,25.07 37.53,24.8 37.54,24.79 37.54,24.77 37.54,24.33 37.97,23.9 40.14,23.9 40.2,23.89 40.24,23.86 40.35,23.75 41.15,23.75 41.19,23.74 41.2,23.7 41.2,20.87 41.2,20.85 41.19,20.84 40.76,20.42 40.75,20.41 40.73,20.4 31.66,20.4 31.6,20.41 31.55,20.45
CSP1 on CONDUCTIVE2: 34.1,24.15 34.08,24.15 34.07,24.16 32.91,25.32 32.9,25.34 32.89,25.36 32.89,30.35 32.91,30.39 32.94,30.4 37.2,30.4 37.24,30.39 37.25,30.35 37.25,25.97 37.25,25.95 37.24,25.94 35.46,24.16 35.45,24.15 35.43,24.15
CSP1 on CONDUCTIVE3: 34.11,24.15 34.09,24.15 34.08,24.16 32.96,25.28 32.95,25.29 32.95,25.31 32.95,30.35 32.96,30.39 33,30.4 37.2,30.4 37.24,30.39 37.25,30.35 37.25,25.97 37.25,25.95 37.24,25.94 35.46,24.16 35.45,24.15 35.43,24.15
CSP2 on TOP: 51.65,21.75 51.54,21.79 51.5,21.9 51.5,25 51.51,25.04 51.55,25.05 52.15,25.05 52.17,25.05 52.19,25.04 52.53,24.7 56,24.7 56.09,24.79 56.1,24.8 56.12,24.8 56.89,24.8 56.93,24.79 56.94,24.75 56.94,22.58 56.96,22.56 56.96,22.54 56.96,22.45 56.95,22.41 56.91,22.4 56.83,22.4 56.19,21.76 56.18,21.75 56.16,21.75
CSP2 on CONDUCTIVE2: 51.87,21.75 51.85,21.75 51.83,21.76 51.51,22.08 51.5,22.1 51.5,22.12 51.5,24.67 51.5,24.69 51.51,24.7 51.85,25.04 51.87,25.05 51.89,25.05 52.15,25.05 52.17,25.05 52.19,25.04 52.43,24.8 56.1,24.8 56.12,24.8 56.14,24.79 56.48,24.44 56.49,24.43 56.5,24.41 56.5,22.14 56.49,22.12 56.48,22.1 56.15,21.76 56.13,21.75 56.11,21.75
DH1 on BOTTOM: 47.15,19.8 47.13,19.81 47,19.97 47.03,20.17 47.06,20.21 47.09,20.24 47.64,20.64 48.1,21.1 48.1,23 47.47,23.63 47.41,23.73 47.4,23.85 47.4,26.54 46.71,27.23 46.2,27.23 46.02,27.31 45.95,27.48 45.95,27.96 45.97,28.05 46.02,28.14 46.17,28.28 46.17,29.11 46.25,29.29 46.42,29.36 46.56,29.36 46.74,29.29 46.81,29.11 46.81,28.48 47.83,27.46 47.88,27.38 47.9,27.28 47.9,23.9 48.53,23.28 48.58,23.2 48.6,23.1 48.6,21 48.58,20.9 48.53,20.82 47.99,20.29 47.59,19.74 47.56,19.71 47.36,19.64 47.18,19.75
DH2 on BOTTOM: 49.35,20.5 49.17,20.57 49.1,20.75 49.1,21.6 49.12,21.69 49.17,21.77 49.75,22.35 49.75,23.21 49.71,23.24 48.9,24.05 48.8,24.05 48.62,24.12 48.55,24.3 48.55,24.5 48.7,24.73 48.98,24.67 49.05,24.6 49.08,24.57 49.75,23.9 50.23,23.9 50.4,23.83 50.48,23.65 50.48,22.28 50.47,22.22 50.4,22.1 49.7,21.4 49.7,20.88 49.71,20.63 49.49,20.5
DH2_Q on TOP: 49.7,24.55 49.66,24.56 49.65,24.6 49.65,25.63 49.65,25.65 49.66,25.66 50.03,26.03 50.05,26.04 50.07,26.05 52.8,26.05 52.83,26.03 52.85,26 52.85,25.34 52.83,25.3 52.8,25.29 52.5,25.29 52.48,25.29 52.46,25.3 52.31,25.45 50.7,25.45 50.2,24.95 50.2,24.6 50.19,24.56 50.15,24.55
DL1 on BOTTOM: 45.74,18.18 45.72,18.18 45.71,18.19 45.01,18.89 45,18.9 45,18.92 45,20.52 44.26,21.26 44.02,21.26 44,21.26 43.99,21.27 43.22,22.04 42.87,22.04 42.83,22.05 42.82,22.09 42.82,22.41 42.83,22.45 42.87,22.46 43.36,22.46 43.38,22.46 43.39,22.45 44.2,21.64 44.86,21.64 44.88,21.64 44.89,21.63 45.69,20.83 45.7,20.82 45.7,20.8 45.7,20.27 45.7,20.25 45.69,20.24 45.65,20.2 45.65,19.3 46.18,18.77 46.18,18.75 46.18,18.23 46.17,18.19 46.13,18.18
DL2 on BOTTOM: 51.12,20.75 50.95,20.82 50.87,21 50.87,21.32 50.82,21.4 50.81,21.49 50.81,21.7 50.81,21.74 50.8,21.77 50.8,21.8 50.8,25.15 50.82,25.23 50.86,25.29 50.9,25.32 51.06,25.49 51.06,26.55 50.86,26.74 50.81,26.82 50.79,26.92 50.79,27.37 50.86,27.54 51.04,27.62 51.25,27.62 51.43,27.54 51.5,27.37 51.5,26.97 51.74,26.73 51.79,26.65 51.81,26.56 51.81,25.57 51.79,25.47 51.74,25.39 51.25,24.9 51.25,21.86 51.47,21.64 51.53,21.55 51.55,21.46 51.55,21.41 51.55,21 51.48,20.82 51.3,20.75
HVDP on TOP: 54.45,11.95 54.38,11.98 54.35,12.05 54.35,12.96 53.41,13.9 52.9,13.9 52.8,14 52.9,14.1 53.45,14.1 53.49,14.09 53.52,14.07 54.83,12.76 54.85,12.73 54.86,12.69 54.86,12.45 54.97,12.08 54.95,11.99 54.87,11.95
LX1 on TOP: 43.17,23.1 43.15,23.1 43.14,23.11 42.86,23.39 42.85,23.4 42.85,23.42 42.85,25.25 42.52,25.57 42.02,25.57 42,25.58 41.99,25.59 41.48,26.1 41.47,26.11 41.46,26.13 41.46,28.14 41.51,28.24 41.61,28.29 42.44,28.29 42.8,28.65 42.8,30.7 42.5,30.7 42.46,30.71 42.45,30.75 42.45,31.25 42.46,31.29 42.5,31.3 42.8,31.3 42.8,38.8 42.84,38.91 42.95,38.95 46.5,38.95 46.61,38.91 46.65,38.8 46.65,26.85 47.15,26.35 47.15,26.33 47.15,23.47 47.15,23.45 47.14,23.44 46.81,23.11 46.8,23.1 46.78,23.1
LX1 on TOP: 48.15,18.4 48.11,18.41 48.1,18.45 48.1,20.2 47.66,20.64 47.65,20.65 47.65,20.67 47.65,21.13 47.65,21.15 47.66,21.16 47.95,21.45 47.95,22.1 47.6,22.45 47.44,22.45 47.4,22.46 47.39,22.5 47.39,23.1 47.4,23.14 47.44,23.15 47.88,23.15 47.9,23.15 47.91,23.14 48.3,22.75 48.3,22.73 48.3,18.45 48.29,18.41 48.25,18.4
LX1 on CONDUCTIVE3: 43.24,23.04 43.22,23.04 43.2,23.05 42.86,23.39 42.85,23.4 42.85,23.42 42.85,26.13 42.85,26.15 42.86,26.16 43.14,26.44 43.15,26.45 43.17,26.45 46.83,26.45 46.85,26.45 46.86,26.44 47.14,26.16 47.15,26.15 47.15,26.13 47.15,23.47 47.15,23.45 47.14,23.44 46.75,23.05 46.73,23.04 46.71,23.04
LX2 on TOP: 48.65,18.4 48.61,18.41 48.6,18.45 48.6,22.78 48.6,22.8 48.61,22.81 48.94,23.14 48.95,23.15 48.97,23.15 49.03,23.23 49.65,23.85 49.65,23.9 49.66,23.94 49.7,23.95 50.15,23.95 50.19,23.94 50.2,23.9 50.2,23.37 50.2,23.35 50.19,23.34 49.3,22.45 49.3,21.42 49.3,21.4 49.29,21.39 48.8,20.9 48.8,18.45 48.79,18.41 48.75,18.4
LX2 on TOP: 53.25,25.2 53.21,25.21 53.2,25.25 53.2,26.1 52.78,26.52 51.95,26.52 51.92,26.52 51.57,26.52 51.55,26.53 51.54,26.54 50.91,27.16 50.9,27.18 50.9,27.2 50.9,38.75 50.94,38.86 51.05,38.9 54.6,38.9 54.71,38.86 54.75,38.75 54.75,33.45 56.9,31.3 58.39,31.3 58.41,31.3 58.43,31.29 58.73,30.98 58.74,30.96 58.75,30.94 58.75,27.15 58.7,27.04 58.6,27 57.2,27 55.44,25.24 55.39,25.21 55.34,25.2
LX2 on CONDUCTIVE2: 55.77,26.95 55.75,26.95 55.73,26.97 55.42,27.28 55.41,27.3 55.4,27.32 55.4,31.15 55.45,31.26 55.55,31.3 58.68,31.3 58.79,31.26 58.83,31.15 58.83,27.1 58.79,26.99 58.68,26.95
LX2 on CONDUCTIVE3: 55.86,26.95 55.84,26.95 55.83,26.96 55.42,27.37 55.41,27.39 55.4,27.41 55.4,31.15 55.45,31.26 55.55,31.3 58.68,31.3 58.79,31.26 58.83,31.15 58.83,27.1 58.79,26.99 58.68,26.95
OUT on TOP: 58.02,12.75 57.99,12.76 57.98,12.8 57.98,17.3 57.98,17.32 57.99,17.33 58.28,17.63 58.28,18.6 58.28,18.66 58.17,18.77 58.16,18.79 58.16,18.81 58.16,21.47 57.56,22.07 57.55,22.08 57.55,22.1 57.55,26.53 57.55,26.55 57.56,26.56 57.74,26.74 57.75,26.75 57.77,26.75 58.7,26.75 58.73,26.74 58.75,26.7 58.75,25.23 59.24,24.73 59.25,24.71 59.25,23.92 59.63,23.54 60.34,23.54 60.4,23.52 60.45,23.49 60.74,23.2 62.12,23.2 62.13,23.2 62.15,23.19 62.71,22.62 71.1,22.62 71.12,22.62 71.14,22.61 71.3,22.45 72.7,22.45 72.9,22.65 72.9,23.1 72.91,23.14 72.95,23.15 75.03,23.15 75.05,23.15 75.06,23.14 76.09,22.11 76.1,22.1 76.1,22.08 76.1,14.75 76.06,14.64 75.95,14.6 61.35,14.6 59.85,13.1 59.85,12.8 59.84,12.76 59.8,12.75
